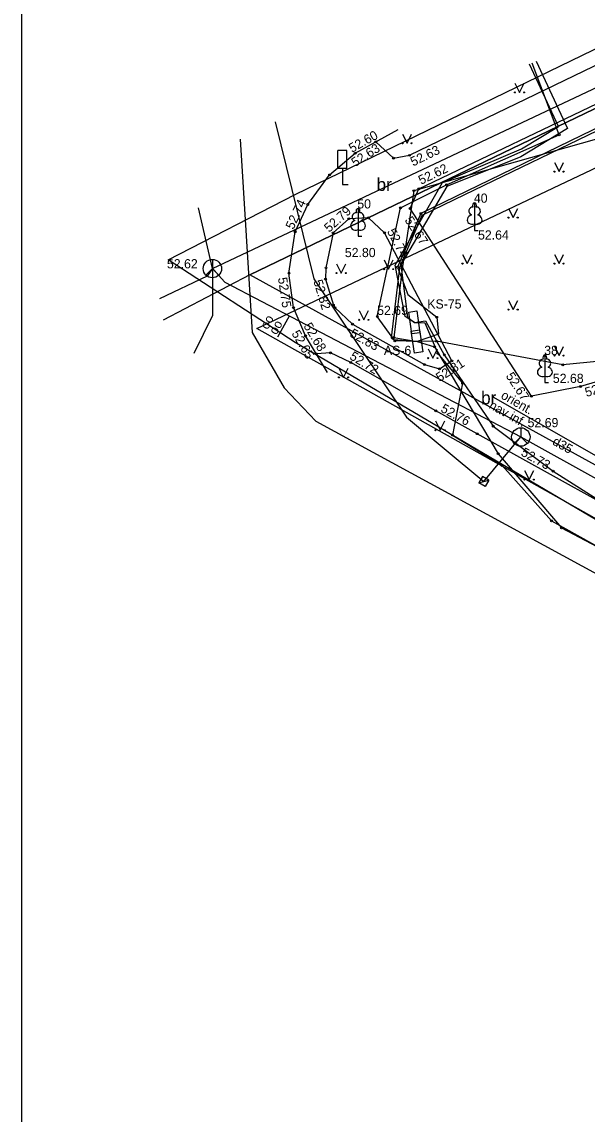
# Model space of a CAD drawing. Extents: x 619806 to 620082, y 405176 to 405386.
# Drawn here: x 619805.8 to 619836.5, y 405248.8 to 405308.1 of the extents above; entities that cross this region are included whole.
import ezdxf

# ---------------------------------------------------------------- set-up
doc = ezdxf.new("R2010")
doc.units = 0
for name, color, linetype in [('24', 7, 'Continuous'), ('APGR_SARK_####_####_#', 7, 'Continuous'), ('APGS_ELEM_####_####_#', 7, 'Continuous'), ('APGS_ELEM_####_TKST_#', 7, 'Continuous'), ('APGS_VADP_ZSPR_####_#', 7, 'Continuous'), ('CELI_CAPM_####_####_#', 7, 'Continuous'), ('CELI_CMAL_####_####_#', 7, 'Continuous'), ('CELI_CSEG_####_TKST_#', 7, 'Continuous'), ('CELI_ELEM_####_####_#', 7, 'Continuous'), ('ELEK_ELEM_####_####_#', 7, 'Continuous'), ('ELEK_ELEM_####_TKST_#', 7, 'Continuous'), ('ELEK_VADP_ZSPR_####_#', 7, 'Continuous'), ('RAMI_PLAN_####_TKST_#', 7, 'Continuous'), ('RAMI_UZMR_####_####_#', 7, 'Continuous'), ('RELJ_AATZ_####_TKST_#', 7, 'Continuous'), ('RELJ_ELEM_####_####_#', 7, 'Continuous'), ('ROBZ_PROJ_####_####_#', 7, 'Continuous'), ('ROBZ_UZMR_####_####_#', 7, 'Continuous'), ('SAKK_ELEM_####_####_#', 7, 'Continuous'), ('SAKK_ELEM_####_TKST_#', 7, 'Continuous'), ('SAKK_IZVK_####_TKST_#', 7, 'Continuous'), ('SAKK_KKAN_####_####_#', 7, 'Continuous'), ('SAKT_ELEM_####_####_#', 7, 'Continuous'), ('SAKT_VADP_KABE_####_#', 7, 'Continuous'), ('TERT_DIAM_####_TKST_#', 7, 'Continuous'), ('TERT_ELEM_####_####_#', 7, 'Continuous'), ('UDTK_VADP_UDEN_####_#', 7, 'Continuous'), ('UDTK_VADP_UDEN_TKST_#', 7, 'Continuous')]:
    doc.layers.add(name, color=color, linetype=linetype)

msp = doc.modelspace()

# ---------------------------------------------------------------- linework, layer by layer
at = {"layer": '24'}
msp.add_line((619931.837, 405349.12), (619818.193, 405294.391), dxfattribs=at)
at = {"layer": 'APGR_SARK_####_####_#'}
for points in [[(619818.56, 405291.467), (619964.609, 405360.731), (619976.198, 405343.424)], [(619990.053, 405197.403), (619966.019, 405209.806), (619941.986, 405222.21), (619880.273, 405256.839), (619818.56, 405291.467)]]:
    msp.add_lwpolyline(points, dxfattribs=at)
at = {"layer": 'APGS_ELEM_####_####_#'}
msp.add_lwpolyline([(619827.411, 405291.393), (619827.592, 405290.207), (619827.147, 405290.139), (619826.966, 405291.325)], close=True, dxfattribs=at)
at = {"layer": 'APGS_VADP_ZSPR_####_#'}
for points in [[(619961.504, 405361.726), (619961.549, 405360.889), (619955.561, 405357.47), (619948.629, 405353.911), (619942.586, 405351.309), (619934.737, 405347.784), (619926.308, 405343.807), (619921.62, 405341.722), (619914.616, 405338.589), (619904.064, 405332.419), (619892.947, 405327.707), (619882.253, 405322.432), (619872.343, 405318.394), (619866.043, 405315.914), (619858.147, 405313.031), (619849.141, 405308.474), (619837.591, 405302.476), (619829.867, 405298.738), (619827.533, 405297.619), (619826.332, 405294.789), (619825.868, 405290.973), (619826.009, 405290.873), (619827.279, 405290.766)], [(619961.504, 405361.726), (619961.582, 405360.944), (619961.547, 405359.255), (619942.312, 405349.715), (619925.4, 405342.794), (619907.997, 405333.971), (619887.51, 405324.581), (619867.415, 405316.417), (619859.827, 405308.06), (619845.28, 405301.51), (619837.164, 405301.798), (619827.1, 405298.963), (619826.475, 405294.709), (619826.025, 405290.988), (619827.279, 405290.766)], [(619904.019, 405332.565), (619892.911, 405327.951), (619882.359, 405322.589), (619872.341, 405318.531), (619866.186, 405316.142), (619865.74, 405316.62), (619866.013, 405316.067), (619858.137, 405313.192), (619849.107, 405308.602), (619837.621, 405302.637), (619837.373, 405303.082), (619837.457, 405302.572), (619827.49, 405297.724), (619826.22, 405294.811), (619826.787, 405293.322), (619828.348, 405292.084), (619828.449, 405291.159), (619827.279, 405290.766)], [(619827.279, 405290.766), (619826.078, 405290.808), (619825.12, 405292.128), (619826.383, 405298.033), (619828.888, 405299.282), (619835.013, 405302.006), (619833.543, 405305.898)], [(619889.151, 405287.633), (619888.839, 405287.188), (619868.564, 405286.313), (619868.359, 405286.853), (619868.361, 405286.315), (619854.776, 405285.354), (619845.67, 405285.418), (619844.273, 405285.984), (619845.432, 405287.623), (619843.395, 405290.297), (619835.199, 405289.5), (619828.336, 405290.779), (619827.279, 405290.766)], [(619827.279, 405290.766), (619828.233, 405290.484), (619831.689, 405284.666), (619835.137, 405280.637), (619844.802, 405275.519), (619857.367, 405269.037), (619864.044, 405264.897), (619871.373, 405258.791), (619881.17, 405253.384), (619884.232, 405252.778), (619898.622, 405244.594), (619910.805, 405239.254), (619917.273, 405236.249), (619923.426, 405231.863), (619936.8, 405224.512), (619938.618, 405223.547), (619972.929, 405204.127)]]:
    msp.add_lwpolyline(points, dxfattribs=at)
at = {"layer": 'CELI_CAPM_####_####_#'}
msp.add_lwpolyline([(619822.407, 405289.087), (619821.22, 405291.076), (619820.56, 405292.61), (619820.317, 405294.479), (619820.65, 405296.727), (619821.337, 405298.216), (619822.526, 405299.822), (619823.912, 405300.999), (619826.246, 405302.294)], dxfattribs=at)
at = {"layer": 'CELI_CMAL_####_####_#'}
for points in [[(619825.042, 405301.626), (619825.997, 405300.736), (619826.865, 405300.888), (619837.411, 405305.982), (619845.924, 405310.094), (619856.691, 405315.252), (619868.203, 405320.761), (619880.848, 405326.828), (619891.162, 405331.79), (619903.487, 405337.685), (619914.792, 405343.079), (619924.282, 405347.611), (619934.782, 405352.643), (619943.391, 405356.735), (619942.998, 405357.499)], [(619901.141, 405301.297), (619895.285, 405291.495), (619886.767, 405291.266), (619876.357, 405290.867), (619868.929, 405290.713), (619868.879, 405291.869), (619865.764, 405291.699), (619865.807, 405290.556), (619863.458, 405290.505), (619853.554, 405290.137), (619841.43, 405289.76), (619840.169, 405289.507), (619836.17, 405288.32), (619833.502, 405287.788), (619826.905, 405297.999), (619827.372, 405299.068), (619837.906, 405304.107), (619846.534, 405308.229), (619856.914, 405313.201), (619868.255, 405318.592), (619880.738, 405324.67), (619889.516, 405328.858), (619904.867, 405336.211)], [(619825.514, 405296.681), (619824.645, 405297.493), (619823.571, 405297.442), (619822.711, 405296.669), (619822.329, 405294.765), (619822.306, 405294.164), (619822.731, 405292.749), (619822.815, 405292.609), (619823.771, 405291.705), (619827.684, 405289.51), (619828.5, 405289.278), (619829.173, 405289.71), (619825.514, 405296.681)], [(619859.084, 405268.056), (619860.53, 405268.999), (619849.818, 405275.016), (619839.176, 405280.957), (619830.556, 405285.755), (619828.304, 405287.001), (619823.674, 405289.625), (619822.58, 405290.149), (619821.807, 405290.092)]]:
    msp.add_lwpolyline(points, dxfattribs=at)
at = {"layer": 'CELI_ELEM_####_####_#'}
for p, q in [((619823.471, 405301.148), (619822.971, 405301.148)), ((619822.971, 405300.179), (619822.971, 405301.148)), ((619823.471, 405300.179), (619823.471, 405301.148)), ((619823.471, 405300.179), (619822.971, 405300.179)), ((619823.225, 405300.179), (619823.225, 405299.301)), ((619823.225, 405299.301), (619823.54, 405299.301))]:
    msp.add_line(p, q, dxfattribs=at)
at = {"layer": 'ELEK_ELEM_####_####_#'}
msp.add_lwpolyline([(619827.272, 405292.427), (619827.439, 405291.239), (619826.994, 405291.177), (619826.827, 405292.365)], close=True, dxfattribs=at)
at = {"layer": 'ELEK_VADP_ZSPR_####_#'}
for points in [[(619827.133, 405291.802), (619826.633, 405292.129), (619826.094, 405294.918), (619828.664, 405299.41), (619832.953, 405301.238), (619834.973, 405302.449), (619833.395, 405305.838)], [(619833.753, 405306.008), (619835.453, 405302.34), (619832.922, 405300.812), (619828.902, 405299.188), (619826.395, 405294.938), (619826.758, 405292.086), (619827.133, 405291.802)], [(619827.133, 405291.802), (619827.743, 405291.898), (619828.762, 405290.038), (619831.425, 405286.162), (619834.68, 405283.716), (619844.517, 405277.484), (619856.454, 405270.832), (619868.451, 405264.196), (619879.269, 405258.357), (619888.402, 405252.405), (619901.725, 405245.908), (619900.354, 405242.567), (619899.734, 405241.465)], [(619827.133, 405291.802), (619827.704, 405291.789), (619828.409, 405290.12), (619829.758, 405288.499), (619829.214, 405285.683), (619831.9, 405284.021), (619834.586, 405281.015), (619842.057, 405276.848), (619851.121, 405270.16), (619862.697, 405262.983), (619874.919, 405256.089), (619882.875, 405253.63), (619881.737, 405251.572)]]:
    msp.add_lwpolyline(points, dxfattribs=at)
at = {"layer": 'RAMI_PLAN_####_TKST_#'}
msp.add_lwpolyline([(619805.793, 405180.095), (619805.793, 405373.209), (619948.393, 405373.209), (619948.393, 405180.095)], close=True, dxfattribs=at)
at = {"layer": 'RAMI_UZMR_####_####_#'}
msp.add_lwpolyline([(619874.687, 405324.979), (619926.719, 405349.544), (619966.669, 405369.042), (620021.738, 405292.03), (620049.703, 405275.476), (620026.189, 405242.287), (620012.147, 405222.917), (619996.603, 405200.928), (619989.997, 405199.173), (619982.328, 405199.155), (619922.669, 405233.014), (619882.137, 405255.756), (619859.084, 405268.056), (619820.646, 405290.715), (619813.744, 405295.206), (619820.645, 405298.752)], close=True, dxfattribs=at)
at = {"layer": 'RELJ_ELEM_####_####_#'}
for centre in [(619825.042, 405301.626), (619835.013, 405302.006), (619823.912, 405300.999), (619825.997, 405300.736), (619826.865, 405300.888), (619822.526, 405299.822), (619828.888, 405299.282), (619827.1, 405298.963), (619827.372, 405299.068), (619821.337, 405298.216), (619826.383, 405298.033), (619826.905, 405297.999), (619823.571, 405297.442), (619824.645, 405297.493), (619827.49, 405297.724), (619820.65, 405296.727), (619822.711, 405296.669), (619825.514, 405296.681), (619820.317, 405294.479), (619822.329, 405294.765), (619826.22, 405294.811), (619826.475, 405294.709), (619822.306, 405294.164), (619822.731, 405292.749), (619820.56, 405292.61), (619822.815, 405292.609), (619825.12, 405292.128), (619828.348, 405292.084), (619823.771, 405291.705), (619821.22, 405291.076), (619826.025, 405290.988), (619826.078, 405290.808), (619828.233, 405290.484), (619828.336, 405290.779), (619821.807, 405290.092), (619822.58, 405290.149), (619828.409, 405290.12), (619828.762, 405290.038), (619829.173, 405289.71), (619823.674, 405289.625), (619827.684, 405289.51), (619828.5, 405289.278), (619835.199, 405289.5), (619829.758, 405288.499), (619836.17, 405288.32), (619833.502, 405287.788), (619828.304, 405287.001), (619831.425, 405286.162), (619829.214, 405285.683), (619830.556, 405285.755), (619831.689, 405284.666), (619831.9, 405284.021), (619834.68, 405283.716), (619834.586, 405281.015), (619835.137, 405280.637)]:
    msp.add_circle(centre, 0.05, dxfattribs=at)
at = {"layer": 'ROBZ_PROJ_####_####_#'}
msp.add_line((619818.193, 405294.391), (619813.477, 405291.929), dxfattribs=at)
at = {"layer": 'ROBZ_UZMR_####_####_#'}
for p, q in [((619818.193, 405294.391), (619931.837, 405349.12)), ((619862.459, 405270.018), (619818.193, 405294.391))]:
    msp.add_line(p, q, dxfattribs=at)
at = {"layer": 'SAKK_ELEM_####_####_#'}
for p, q in [((619816.151, 405294.73), (619816.505, 405294.376)), ((619832.922, 405285.576), (619833.276, 405285.222))]:
    msp.add_line(p, q, dxfattribs=at)
for points in [[(619816.151, 405295.23), (619816.151, 405294.73), (619815.797, 405294.376)], [(619832.922, 405286.076), (619832.922, 405285.576), (619832.568, 405285.222)]]:
    msp.add_lwpolyline(points, dxfattribs=at)
for centre in [(619816.151, 405294.73), (619832.922, 405285.576)]:
    msp.add_circle(centre, 0.5, dxfattribs=at)
at = {"layer": 'SAKK_IZVK_####_TKST_#'}
msp.add_line((619819.709, 405291.026), (619820.337, 405292.162), dxfattribs=at)
at = {"layer": 'SAKK_KKAN_####_####_#'}
for points in [[(619816.151, 405294.73), (619815.403, 405298.041)], [(619816.151, 405294.73), (619815.871, 405294.324), (619813.285, 405293.093)], [(619816.151, 405294.73), (619816.825, 405294), (619832.922, 405285.576), (619895.115, 405251.073), (619918.714, 405238.138)]]:
    msp.add_lwpolyline(points, dxfattribs=at)
at = {"layer": 'SAKT_ELEM_####_####_#'}
for p, q in [((619830.833, 405283.43), (619830.633, 405283.091)), ((619831.179, 405283.227), (619830.833, 405283.43))]:
    msp.add_line(p, q, dxfattribs=at)
msp.add_lwpolyline([(619830.633, 405283.091), (619831.179, 405283.227), (619830.979, 405282.888)], close=True, dxfattribs=at)
at = {"layer": 'SAKT_VADP_KABE_####_#'}
msp.add_line((619830.906, 405283.159), (619832.922, 405285.576), dxfattribs=at)
for points in [[(619816.151, 405294.73), (619838.42, 405305.23), (619866.149, 405318.697), (619899.278, 405334.929), (619937.202, 405353.635), (619962.924, 405366.289), (619964.424, 405369.208)], [(619819.567, 405302.713), (619821.659, 405294.168), (619826.714, 405286.655), (619830.906, 405283.159)], [(619817.668, 405301.762), (619818.308, 405291.251), (619820.058, 405288.244), (619821.78, 405286.435), (619865.996, 405262.382), (619894.538, 405246.913), (619928.954, 405228.717), (619988.18, 405195.595)], [(619816.151, 405294.73), (619816.151, 405292.178), (619815.146, 405290.119)]]:
    msp.add_lwpolyline(points, dxfattribs=at)
at = {"layer": 'TERT_ELEM_####_####_#'}
for p, q in [((619832.6, 405304.807), (619832.85, 405304.307)), ((619832.85, 405304.307), (619833.1, 405304.807)), ((619826.484, 405302.041), (619826.734, 405301.541)), ((619826.734, 405301.541), (619826.984, 405302.041)), ((619834.75, 405300.5), (619835, 405300)), ((619835, 405300), (619835.25, 405300.5)), ((619832.25, 405298), (619832.5, 405297.5)), ((619832.5, 405297.5), (619832.75, 405298)), ((619824.071, 405296.847), (619824.071, 405296.5)), ((619830.409, 405297.157), (619830.409, 405296.81)), ((619824.071, 405296.5), (619824.271, 405296.5)), ((619830.409, 405296.81), (619830.609, 405296.81)), ((619825.486, 405295.2), (619825.736, 405294.7)), ((619825.736, 405294.7), (619825.986, 405295.2)), ((619829.75, 405295.5), (619830, 405295)), ((619830, 405295), (619830.25, 405295.5)), ((619834.75, 405295.5), (619835, 405295)), ((619835, 405295), (619835.25, 405295.5)), ((619822.902, 405294.984), (619823.152, 405294.484)), ((619823.152, 405294.484), (619823.402, 405294.984)), ((619832.25, 405293), (619832.5, 405292.5)), ((619832.5, 405292.5), (619832.75, 405293)), ((619824.133, 405292.446), (619824.383, 405291.946)), ((619824.383, 405291.946), (619824.633, 405292.446)), ((619827.885, 405290.361), (619828.135, 405289.861)), ((619828.135, 405289.861), (619828.385, 405290.361)), ((619834.75, 405290.5), (619835, 405290)), ((619835, 405290), (619835.25, 405290.5)), ((619823.034, 405289.319), (619823.284, 405288.819)), ((619823.284, 405288.819), (619823.534, 405289.319)), ((619834.232, 405288.881), (619834.232, 405288.534)), ((619834.232, 405288.534), (619834.432, 405288.534)), ((619828.287, 405286.449), (619828.537, 405285.949)), ((619828.537, 405285.949), (619828.787, 405286.449)), ((619833.128, 405283.759), (619833.378, 405283.259)), ((619833.378, 405283.259), (619833.628, 405283.759))]:
    msp.add_line(p, q, dxfattribs=at)
for points in [[(619830.409, 405298.31), (619830.409, 405297.157)], [(619830.499, 405298.078), (619830.498, 405298.079)], [(619824.071, 405298), (619824.071, 405296.847)], [(619824.161, 405297.768), (619824.16, 405297.769)], [(619834.232, 405290.034), (619834.232, 405288.881)], [(619834.322, 405289.802), (619834.321, 405289.803)]]:
    msp.add_lwpolyline(points, dxfattribs=at)
for centre, radius in [((619832.599, 405304.306), 0.028), ((619833.099, 405304.306), 0.0263), ((619826.484, 405301.541), 0.028), ((619826.984, 405301.541), 0.0263), ((619834.75, 405300), 0.028), ((619835.25, 405300), 0.0263), ((619832.25, 405297.5), 0.028), ((619832.75, 405297.5), 0.0263), ((619822.901, 405294.484), 0.028), ((619823.401, 405294.484), 0.0263), ((619825.486, 405294.7), 0.028), ((619825.986, 405294.7), 0.0263), ((619829.75, 405295), 0.028), ((619830.25, 405295), 0.0263), ((619834.75, 405295), 0.028), ((619835.25, 405295), 0.0263), ((619832.25, 405292.5), 0.028), ((619832.75, 405292.5), 0.0263), ((619824.133, 405291.946), 0.028), ((619824.633, 405291.946), 0.0263), ((619827.884, 405289.861), 0.028), ((619828.384, 405289.861), 0.0263), ((619834.75, 405290), 0.028), ((619835.25, 405290), 0.0263), ((619823.033, 405288.819), 0.028), ((619823.533, 405288.819), 0.0263), ((619828.287, 405285.948), 0.028), ((619828.787, 405285.948), 0.0263), ((619833.128, 405283.259), 0.028), ((619833.628, 405283.259), 0.0263)]:
    msp.add_circle(centre, radius, dxfattribs=at)
for centre, major_axis, ratio, start_param, end_param in [((619830.281, 405297.865), (-0.039, -0.212), 0.861323, 3.141593, 6.283185), ((619830.409, 405298.16), (0, -0.15), 0.707107, 3.14537, 5.287485), ((619830.409, 405298.16), (0, -0.15), 0.707107, 0.995701, 3.137816), ((619830.537, 405297.865), (0.039, -0.212), 0.861323, 0, 3.141593), ((619823.943, 405297.555), (-0.039, -0.212), 0.861323, 3.141593, 6.283185), ((619824.071, 405297.85), (0, -0.15), 0.707107, 3.14537, 5.287485), ((619824.071, 405297.85), (0, -0.15), 0.707107, 0.995701, 3.137816), ((619824.199, 405297.555), (0.039, -0.212), 0.861323, 0, 3.141593), ((619830.319, 405297.403), (0.307, 0.095), 0.814445, 1.570796, 4.752015), ((619830.499, 405297.403), (-0.307, 0.095), 0.814445, 1.531171, 4.712389), ((619823.981, 405297.093), (0.307, 0.095), 0.814445, 1.570796, 4.752015), ((619824.161, 405297.093), (-0.307, 0.095), 0.814445, 1.531171, 4.712389), ((619834.104, 405289.589), (-0.039, -0.212), 0.861323, 3.141593, 6.283185), ((619834.232, 405289.884), (0, -0.15), 0.707107, 3.14537, 5.287485), ((619834.232, 405289.884), (0, -0.15), 0.707107, 0.995701, 3.137816), ((619834.36, 405289.589), (0.039, -0.212), 0.861323, 0, 3.141593), ((619834.142, 405289.127), (0.307, 0.095), 0.814445, 1.570796, 4.752015), ((619834.322, 405289.127), (-0.307, 0.095), 0.814445, 1.531171, 4.712389)]:
    msp.add_ellipse(centre, major_axis=major_axis, ratio=ratio, start_param=start_param, end_param=end_param, dxfattribs=at)
at = {"layer": 'UDTK_VADP_UDEN_####_#'}
msp.add_lwpolyline([(619840.294, 405282.668), (619831.461, 405287.722)], dxfattribs=at)

# ---------------------------------------------------------------- texts
at = {"layer": 'APGS_ELEM_####_TKST_#'}
msp.add_text('AS-6', height=0.5, dxfattribs=at).set_placement((619825.477, 405290.033))
at = {"layer": 'CELI_CSEG_####_TKST_#'}
for p in [(619825.077, 405298.952), (619830.759, 405287.356)]:
    msp.add_text('br', height=0.7, dxfattribs=at).set_placement(p)
at = {"layer": 'ELEK_ELEM_####_TKST_#'}
msp.add_text('KS-75', height=0.5, dxfattribs=at).set_placement((619827.838, 405292.559))
at = {"layer": 'RELJ_AATZ_####_TKST_#'}
for s, rotation, p in [(' 52.60', 29.02446, (619823.579, 405300.927)), (' 52.63', 32.77213, (619823.752, 405300.137)), (' 52.63', 25.78178, (619826.9, 405300.2)), (' 52.62', 25.56439, (619827.331, 405299.203)), (' 52.74', 65.15736, (619820.479, 405296.653)), (' 52.79', 41.95038, (619822.361, 405296.548)), (' 52.67', 302.86521, (619826.485, 405297.521)), (' 52.74', 297.69448, (619825.547, 405296.916)), (' 52.75', 278.32815, (619819.69, 405294.407)), (' 52.82', 286.71782, (619821.584, 405294.227)), (' 52.68', 300.81797, (619820.995, 405291.767)), (' 52.65', 300.36708, (619820.345, 405291.366)), (' 52.83', 330.70972, (619823.414, 405291.155)), (' 52.72', 328.45438, (619823.412, 405289.934)), (' 52.81', 32.69648, (619828.35, 405288.452)), (' 52.67', 303.15451, (619831.982, 405289.048)), (' 52.66', 16.53216, (619836.312, 405287.698)), (' 52.76', 331.04486, (619828.358, 405287.067)), (' 52.73', 330.89914, (619832.722, 405284.686))]:
    msp.add_text(s, height=0.5, rotation=rotation, dxfattribs=at).set_placement(p)
for s, p in [(' 52.64', (619830.409, 405296.31)), (' 52.80', (619823.169, 405295.355)), (' 52.69', (619824.923, 405292.208)), (' 52.68', (619834.477, 405288.516))]:
    msp.add_text(s, height=0.5, dxfattribs=at).set_placement(p)
at = {"layer": 'SAKK_ELEM_####_TKST_#'}
for s, p in [(' 52.62', (619813.496, 405294.743)), (' 52.69', (619833.105, 405286.108))]:
    msp.add_text(s, height=0.5, dxfattribs=at).set_placement(p)
at = {"layer": 'SAKK_IZVK_####_TKST_#'}
for p in [(619819.155, 405291.38), (619819.631, 405291.095)]:
    msp.add_text('oo', height=0.5, rotation=61.00628, dxfattribs=at).set_placement(p)
at = {"layer": 'TERT_DIAM_####_TKST_#'}
for s, p in [(' 40', (619830.184, 405298.31)), (' 50', (619823.846, 405298)), (' 38', (619834.007, 405290.034))]:
    msp.add_text(s, height=0.5, dxfattribs=at).set_placement(p)
at = {"layer": 'UDTK_VADP_UDEN_TKST_#'}
for s, p in [('orient.', (619831.795, 405287.704)), ('nav inf.', (619831.155, 405287.167)), ('d35', (619834.595, 405285.198))]:
    msp.add_text(s, height=0.5, rotation=330.22373, dxfattribs=at).set_placement(p)

doc.saveas('drawing.dxf')
